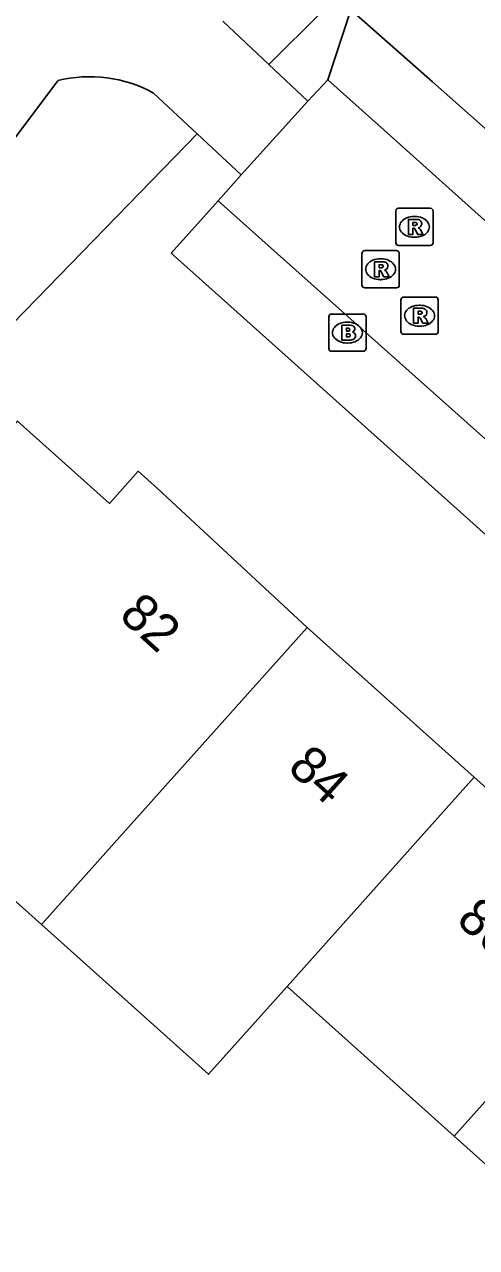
# Model space of a CAD drawing. Extents: x 159040 to 160094, y 381214 to 382518.
# Drawn here: x 159476.76 to 159488.91, y 381770.11 to 381802.95 of the extents above; entities that cross this region are included whole.
import ezdxf

# ---------------------------------------------------------------- set-up
doc = ezdxf.new("R2010")
doc.units = 0
for name, color, linetype in [('IMGEO_Brandkraan', 7, 'Continuous'), ('IMGEO_Groenvoorziening', 7, 'Continuous'), ('IMGEO_Pand', 7, 'Continuous'), ('IMGEO_Pand_nummerreeks', 7, 'Continuous'), ('IMGEO_Rijbaan_lokaal_open', 7, 'Continuous'), ('IMGEO_Rioolput', 7, 'Continuous'), ('IMGEO_Voetpad_gesloten', 7, 'Continuous'), ('IMGEO_Voetpad_open', 7, 'Continuous')]:
    doc.layers.add(name, color=color, linetype=linetype)

msp = doc.modelspace()

# ---------------------------------------------------------------- linework, layer by layer
at = {"layer": 'IMGEO_Brandkraan'}
for p, q in [((159484.937, 381794.247), (159484.937, 381795.099)), ((159485.012, 381795.173), (159485.864, 381795.173)), ((159485.938, 381795.099), (159485.938, 381794.247)), ((159485.425, 381794.953), (159485.45, 381794.953)), ((159485.864, 381794.173), (159485.012, 381794.173)), ((159485.448, 381794.393), (159485.423, 381794.393))]:
    msp.add_line(p, q, dxfattribs=at)
for points in [[(159484.937, 381794.247), (159484.937, 381795.099)], [(159485.012, 381795.173), (159485.864, 381795.173)], [(159485.938, 381795.099), (159485.938, 381794.247)], [(159485.285, 381794.873), (159485.285, 381794.473), (159485.498, 381794.473)], [(159485.516, 381794.873), (159485.285, 381794.873)], [(159485.464, 381794.792), (159485.41, 381794.792), (159485.41, 381794.716)], [(159485.41, 381794.716), (159485.463, 381794.716)], [(159485.472, 381794.64), (159485.41, 381794.64), (159485.41, 381794.559)], [(159485.41, 381794.559), (159485.472, 381794.559)], [(159485.864, 381794.173), (159485.012, 381794.173)]]:
    msp.add_lwpolyline(points, dxfattribs=at)
for centre, radius, start, end in [((159485.014, 381795.097), 0.0765, 91.552, 178.448), ((159485.014, 381795.097), 0.0765, 91.552, 178.448), ((159485.862, 381795.097), 0.0765, 1.552, 88.448), ((159485.862, 381795.097), 0.0765, 1.552, 88.448), ((159485.465, 381794.754), 0.0379, 267.8285, 90.9355), ((159485.52, 381794.728), 0.145, 59.4692, 91.5367), ((159485.545, 381794.775), 0.0922, 285.5137, 58.1501), ((159485.473, 381794.599), 0.0404, 269.8759, 90.5077), ((159485.504, 381794.724), 0.251, 268.6676, 293.5347), ((159485.55, 381794.583), 0.105, 301.3115, 78.989), ((159485.014, 381794.249), 0.0765, 181.552, 268.448), ((159485.014, 381794.249), 0.0765, 181.552, 268.448), ((159485.862, 381794.249), 0.0765, 271.552, 358.448), ((159485.862, 381794.249), 0.0765, 271.552, 358.448)]:
    msp.add_arc(centre, radius, start, end, dxfattribs=at)
for centre, major_axis, ratio, start_param, end_param in [((159485.424, 381794.673), (-0.387, 0.002), 0.722429, 4.712389, 7.853982), ((159485.449, 381794.673), (-0.39, 0.002), 0.717154, 1.570796, 4.712389)]:
    msp.add_ellipse(centre, major_axis=major_axis, ratio=ratio, start_param=start_param, end_param=end_param, dxfattribs=at)
at = {"layer": 'IMGEO_Groenvoorziening'}
for points in [[(159509.885, 381839.344), (159482.865, 381805.051), (159484.748, 381803.285), (159483.331, 381801.872)], [(159462.202, 381778.537), (159470.575, 381788.888), (159481.405, 381800.01)]]:
    msp.add_lwpolyline(points, dxfattribs=at)
at = {"layer": 'IMGEO_Pand'}
for points in [[(159473.576, 381783.985), (159474.721, 381785.263), (159472.259, 381787.467), (159476.579, 381792.296), (159479.045, 381790.089), (159479.818, 381790.953), (159480.34, 381790.486), (159484.353, 381786.758)], [(159484.353, 381786.758), (159479.328, 381781.139), (159477.218, 381778.778)], [(159484.353, 381786.758), (159488.841, 381782.739)], [(159483.817, 381777.121), (159488.841, 381782.739)], [(159488.841, 381782.739), (159493.329, 381778.719)], [(159477.218, 381778.778), (159473.981, 381781.672)], [(159483.817, 381777.121), (159481.709, 381774.763), (159477.218, 381778.778)], [(159493.329, 381778.719), (159488.306, 381773.102)], [(159488.306, 381773.102), (159483.817, 381777.121)], [(159492.904, 381768.986), (159488.306, 381773.102)]]:
    msp.add_lwpolyline(points, dxfattribs=at)
at = {"layer": 'IMGEO_Rijbaan_lokaal_open'}
for points in [[(159484.913, 381801.464), (159484.376, 381800.892)], [(159505.502, 381782.995), (159486.504, 381800.037), (159484.913, 381801.464)], [(159484.376, 381800.892), (159482.586, 381798.907)], [(159482.586, 381798.907), (159481.965, 381798.214)], [(159481.965, 381798.214), (159483.564, 381796.789), (159502.62, 381779.807)]]:
    msp.add_lwpolyline(points, dxfattribs=at)
at = {"layer": 'IMGEO_Rioolput'}
for p, q in [((159486.812, 381798.012), (159487.664, 381798.012)), ((159486.737, 381797.086), (159486.737, 381797.938)), ((159487.225, 381797.792), (159487.25, 381797.792)), ((159487.738, 381797.938), (159487.738, 381797.086)), ((159487.248, 381797.232), (159487.223, 381797.232)), ((159485.829, 381795.949), (159485.829, 381796.801)), ((159485.904, 381796.875), (159486.756, 381796.875)), ((159487.664, 381797.012), (159486.812, 381797.012)), ((159486.83, 381796.801), (159486.83, 381795.949)), ((159486.317, 381796.655), (159486.342, 381796.655)), ((159486.34, 381796.095), (159486.315, 381796.095)), ((159486.756, 381795.875), (159485.904, 381795.875)), ((159486.875, 381794.702), (159486.875, 381795.554)), ((159486.95, 381795.628), (159487.802, 381795.628)), ((159487.363, 381795.408), (159487.388, 381795.408)), ((159487.876, 381795.554), (159487.876, 381794.702)), ((159487.386, 381794.848), (159487.361, 381794.848)), ((159487.802, 381794.628), (159486.95, 381794.628))]:
    msp.add_line(p, q, dxfattribs=at)
for points in [[(159486.812, 381798.012), (159487.664, 381798.012)], [(159486.737, 381797.086), (159486.737, 381797.938)], [(159487.326, 381797.71), (159487.074, 381797.712), (159487.074, 381797.312)], [(159487.738, 381797.938), (159487.738, 381797.086)], [(159487.074, 381797.312), (159487.198, 381797.312), (159487.198, 381797.474), (159487.209, 381797.474)], [(159487.252, 381797.631), (159487.198, 381797.631), (159487.198, 381797.55)], [(159487.198, 381797.55), (159487.25, 381797.55)], [(159487.256, 381797.445), (159487.327, 381797.312), (159487.467, 381797.312), (159487.402, 381797.438)], [(159485.829, 381795.949), (159485.829, 381796.801)], [(159485.904, 381796.875), (159486.756, 381796.875)], [(159487.664, 381797.012), (159486.812, 381797.012)], [(159486.83, 381796.801), (159486.83, 381795.949)], [(159486.418, 381796.573), (159486.166, 381796.575), (159486.166, 381796.175)], [(159486.344, 381796.494), (159486.29, 381796.494), (159486.29, 381796.413)], [(159486.29, 381796.413), (159486.342, 381796.413)], [(159486.166, 381796.175), (159486.29, 381796.175), (159486.29, 381796.337), (159486.301, 381796.337)], [(159486.348, 381796.308), (159486.419, 381796.175), (159486.559, 381796.175), (159486.494, 381796.301)], [(159486.756, 381795.875), (159485.904, 381795.875)], [(159486.875, 381794.702), (159486.875, 381795.554)], [(159486.95, 381795.628), (159487.802, 381795.628)], [(159487.876, 381795.554), (159487.876, 381794.702)], [(159487.464, 381795.326), (159487.212, 381795.328), (159487.212, 381794.928)], [(159487.212, 381794.928), (159487.336, 381794.928), (159487.336, 381795.09), (159487.347, 381795.09)], [(159487.39, 381795.247), (159487.336, 381795.247), (159487.336, 381795.166)], [(159487.336, 381795.166), (159487.388, 381795.166)], [(159487.394, 381795.061), (159487.465, 381794.928), (159487.605, 381794.928), (159487.54, 381795.054)], [(159487.802, 381794.628), (159486.95, 381794.628)]]:
    msp.add_lwpolyline(points, dxfattribs=at)
for centre, radius, start, end in [((159486.814, 381797.936), 0.0765, 91.552, 178.448), ((159486.814, 381797.936), 0.0765, 91.552, 178.448), ((159487.662, 381797.936), 0.0765, 1.552, 88.448), ((159487.662, 381797.936), 0.0765, 1.552, 88.448), ((159487.325, 381797.6), 0.109, 350.3612, 89.416), ((159487.208, 381797.421), 0.0533, 26.0293, 88.6989), ((159487.234, 381797.739), 0.19, 274.7715, 282.9687), ((159487.258, 381797.535), 0.0964, 77.0061, 93.1865), ((159487.272, 381797.592), 0.0378, 276.6634, 79.6772), ((159487.323, 381797.6), 0.112, 277.5842, 350.9817), ((159487.307, 381797.385), 0.108, 29.5134, 73.7905), ((159486.814, 381797.088), 0.0765, 181.552, 268.448), ((159486.814, 381797.088), 0.0765, 181.552, 268.448), ((159487.662, 381797.088), 0.0765, 271.552, 358.448), ((159487.662, 381797.088), 0.0765, 271.552, 358.448), ((159485.906, 381796.799), 0.0765, 91.552, 178.448), ((159485.906, 381796.799), 0.0765, 91.552, 178.448), ((159486.754, 381796.799), 0.0765, 1.552, 88.448), ((159486.754, 381796.799), 0.0765, 1.552, 88.448), ((159486.326, 381796.602), 0.19, 274.7715, 282.9687), ((159486.35, 381796.398), 0.0964, 77.0061, 93.1865), ((159486.364, 381796.455), 0.0378, 276.6634, 79.6772), ((159486.417, 381796.463), 0.109, 350.3612, 89.416), ((159486.415, 381796.463), 0.112, 277.5842, 350.9817), ((159486.3, 381796.284), 0.0533, 26.0293, 88.6989), ((159486.399, 381796.248), 0.108, 29.5134, 73.7905), ((159485.906, 381795.951), 0.0765, 181.552, 268.448), ((159485.906, 381795.951), 0.0765, 181.552, 268.448), ((159486.754, 381795.951), 0.0765, 271.552, 358.448), ((159486.754, 381795.951), 0.0765, 271.552, 358.448), ((159486.952, 381795.552), 0.0765, 91.552, 178.448), ((159486.952, 381795.552), 0.0765, 91.552, 178.448), ((159487.8, 381795.552), 0.0765, 1.552, 88.448), ((159487.8, 381795.552), 0.0765, 1.552, 88.448), ((159487.346, 381795.037), 0.0533, 26.0293, 88.6989), ((159487.372, 381795.355), 0.19, 274.7715, 282.9687), ((159487.396, 381795.151), 0.0964, 77.0061, 93.1865), ((159487.41, 381795.208), 0.0378, 276.6634, 79.6772), ((159487.463, 381795.216), 0.109, 350.3612, 89.416), ((159487.461, 381795.216), 0.112, 277.5842, 350.9817), ((159487.445, 381795.001), 0.108, 29.5134, 73.7905), ((159486.952, 381794.704), 0.0765, 181.552, 268.448), ((159486.952, 381794.704), 0.0765, 181.552, 268.448), ((159487.8, 381794.704), 0.0765, 271.552, 358.448), ((159487.8, 381794.704), 0.0765, 271.552, 358.448)]:
    msp.add_arc(centre, radius, start, end, dxfattribs=at)
for centre, major_axis, ratio, start_param, end_param in [((159487.224, 381797.512), (-0.387, 0.002), 0.722429, 4.712389, 7.853982), ((159487.249, 381797.512), (-0.39, 0.002), 0.717154, 1.570796, 4.712389), ((159486.316, 381796.375), (-0.387, 0.002), 0.722429, 4.712389, 7.853982), ((159486.341, 381796.375), (-0.39, 0.002), 0.717154, 1.570796, 4.712389), ((159487.362, 381795.128), (-0.387, 0.002), 0.722429, 4.712389, 7.853982), ((159487.387, 381795.128), (-0.39, 0.002), 0.717154, 1.570796, 4.712389)]:
    msp.add_ellipse(centre, major_axis=major_axis, ratio=ratio, start_param=start_param, end_param=end_param, dxfattribs=at)
at = {"layer": 'IMGEO_Voetpad_gesloten'}
for points in [[(159482.091, 381803.035), (159483.331, 381801.872)], [(159483.331, 381801.872), (159484.376, 381800.892)], [(159477.659, 381801.438), (159461.121, 381779.412)], [(159481.405, 381800.01), (159480.232, 381801.105)], [(159482.586, 381798.907), (159481.405, 381800.01)]]:
    msp.add_lwpolyline(points, dxfattribs=at)
msp.add_arc((159478.521, 381797.995), 3.55, 61.1903, 104.0611, dxfattribs=at)
at = {"layer": 'IMGEO_Voetpad_open'}
for points in [[(159484.913, 381801.464), (159485.533, 381803.343)], [(159485.533, 381803.343), (159487.723, 381801.404), (159503.573, 381787.369), (159506.301, 381784.953)], [(159500.454, 381779.131), (159482.304, 381795.376), (159480.705, 381796.807), (159481.965, 381798.214)]]:
    msp.add_lwpolyline(points, dxfattribs=at)

# ---------------------------------------------------------------- texts
at = {"layer": 'IMGEO_Pand_nummerreeks'}
for s, rotation, p in [('82', 317.9182, (159479.268, 381787.03)), ('84', 317.9162, (159483.797, 381782.939)), ('86', 317.9182, (159488.326, 381778.851))]:
    msp.add_text(s, height=1, rotation=rotation, dxfattribs=at).set_placement(p)

doc.saveas('drawing.dxf')
